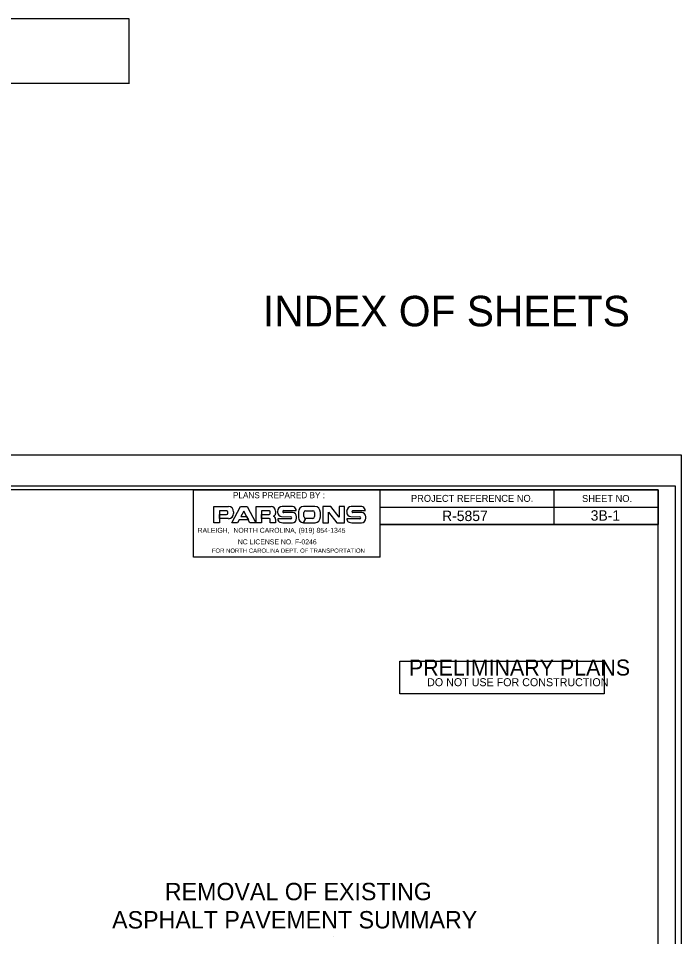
# Model space of a CAD drawing. Extents: x 1729625 to 1732014, y 538843 to 541329.
# Drawn here: x 1731022 to 1731499, y 540668 to 541329 of the extents above; entities that cross this region are included whole.
import ezdxf

# ---------------------------------------------------------------- set-up
doc = ezdxf.new("R2010")
doc.units = 0
for name, color, linetype in [('Old_Level_2', 7, 'Continuous'), ('Prop Horizontal Alignment', 7, 'Continuous'), ('Sheet Cutting Line CELL', 7, 'Continuous'), ('Sheet Data Field CELL', 7, 'Continuous'), ('Sheet Plot Border Inside CELL', 7, 'Continuous'), ('Sheet Plot Border Outside CELL', 7, 'Continuous'), ('Sheet Sticker Exception Certification CELL', 7, 'Continuous'), ('Sheet Sticker Preliminary CELL', 7, 'Continuous'), ('Sheet Summary CELL', 7, 'Continuous')]:
    doc.layers.add(name, color=color, linetype=linetype)

msp = doc.modelspace()

# ---------------------------------------------------------------- linework, layer by layer
at = {"layer": 'Old_Level_2'}
for p, q in [((1731148.02, 540989.91), (1731282.42, 540989.91)), ((1731148.02, 540941.49), (1731148.02, 540989.91)), ((1731282.42, 540941.49), (1731282.42, 540989.91)), ((1731218.6, 540977.9), (1731211.95, 540977.89)), ((1731213.03, 540974.91), (1731222.03, 540974.91)), ((1731235.48, 540977.9), (1731227.35, 540977.89)), ((1731268.36, 540977.9), (1731261.71, 540977.89)), ((1731262.78, 540974.91), (1731271.79, 540974.91)), ((1731172.84, 540973.16), (1731172.84, 540973.85)), ((1731176.92, 540974.07), (1731176.92, 540972.92)), ((1731203.33, 540972.92), (1731203.33, 540974.23)), ((1731207.12, 540974.61), (1731207.12, 540972.85)), ((1731208.6, 540974.31), (1731208.6, 540973.84)), ((1731211.54, 540970.62), (1731218.1, 540970.48)), ((1731219.46, 540973.46), (1731213.03, 540973.46)), ((1731222.31, 540969.48), (1731222.31, 540970.4)), ((1731223.67, 540973.92), (1731223.67, 540970.02)), ((1731227.21, 540966.19), (1731228.76, 540969.33)), ((1731227.63, 540970.56), (1731227.63, 540973.54)), ((1731228.76, 540974.77), (1731234.07, 540974.77)), ((1731235.2, 540973.54), (1731235.2, 540970.56)), ((1731239.45, 540970.32), (1731239.45, 540973.62)), ((1731258.36, 540974.31), (1731258.36, 540973.84)), ((1731261.3, 540970.62), (1731267.86, 540970.48)), ((1731269.21, 540973.46), (1731262.78, 540973.46)), ((1731272.07, 540969.48), (1731272.07, 540970.4)), ((1731212.38, 540966.19), (1731219.25, 540966.19)), ((1731227.2, 540966.19), (1731235.63, 540966.19)), ((1731262.14, 540966.19), (1731269.01, 540966.19)), ((1731282.42, 540941.49), (1731148.02, 540941.49))]:
    msp.add_line(p, q, dxfattribs=at)
for points in [[(1731171.98, 540974.77), (1731166.82, 540974.77), (1731166.82, 540972.09), (1731166.89, 540969.1), (1731166.89, 540966.19), (1731162.73, 540966.19), (1731162.73, 540977.9), (1731173.34, 540977.9)], [(1731202.83, 540974.76), (1731197.04, 540974.76), (1731197.04, 540972.16), (1731197.04, 540969.33), (1731197.04, 540966.2), (1731193.18, 540966.19), (1731193.18, 540977.9), (1731204.04, 540977.9)], [(1731173.34, 540969.1), (1731166.89, 540969.1), (1731166.82, 540972.09), (1731171.84, 540972.09)], [(1731207.12, 540968.72), (1731207.12, 540966.2), (1731203.19, 540966.2), (1731203.19, 540968.87), (1731202.68, 540969.33), (1731197.04, 540969.33), (1731197.04, 540972.16), (1731202.61, 540972.16)], [(1731218.1, 540969.03), (1731208.74, 540969.03), (1731208.74, 540968.79)], [(1731234.07, 540969.33), (1731228.76, 540969.33), (1731227.21, 540966.19), (1731235.63, 540966.19)], [(1731267.86, 540969.03), (1731258.5, 540969.03), (1731258.5, 540968.79)]]:
    msp.add_lwpolyline(points, dxfattribs=at)
for points in [[(1731175.58, 540966.19), (1731182.01, 540977.9), (1731186.69, 540977.9), (1731193.05, 540966.19), (1731188.67, 540966.19), (1731184.21, 540974.38), (1731182.15, 540970.63), (1731186.26, 540970.63), (1731187.6, 540968.18), (1731180.88, 540968.18), (1731179.82, 540966.19)], [(1731241.23, 540977.9), (1731241.23, 540966.19), (1731245.2, 540966.19), (1731245.2, 540973.77), (1731251.28, 540966.19), (1731256.87, 540966.19), (1731256.87, 540977.9), (1731253.05, 540977.9), (1731253.05, 540970.1), (1731246.89, 540977.9)]]:
    msp.add_lwpolyline(points, close=True, dxfattribs=at)
for centre, major_axis, ratio, start_param, end_param in [((1731173.34, 540974.07), (0, 3.83), 0.93676, 4.712389, 6.283185), ((1731204.04, 540974.61), (0, 3.29), 0.934072, 4.712389, 6.283185), ((1731211.96, 540974.3), (0, 3.6), 0.934072, 0, 1.570796), ((1731213.03, 540974.19), (0, 0.727), 0.934072, 0, 3.141593), ((1731218.6, 540972.92), (0, 4.97), 0.934072, 5.902203, 6.283185), ((1731219.32, 540974.84), (0, 2.91), 0.934072, 4.738699, 5.901866), ((1731227.35, 540973.92), (0, 3.98), 0.924824, 0, 1.570796), ((1731235.48, 540973.61), (0, 4.28), 0.924824, 4.712389, 6.283185), ((1731261.71, 540974.3), (0, 3.6), 0.934072, 0, 1.570796), ((1731262.79, 540974.19), (0, 0.727), 0.934072, 0, 3.141593), ((1731268.36, 540972.92), (0, 4.97), 0.934072, 5.902203, 6.283185), ((1731269.07, 540974.84), (0, 2.91), 0.934072, 4.738699, 5.901866), ((1731171.83, 540973.15), (0, 1.07), 0.93676, 3.141593, 4.712389), ((1731171.98, 540973.84), (0, 0.918), 0.93676, 4.712389, 6.283185), ((1731173.34, 540972.92), (0, 3.83), 0.93676, 3.141593, 4.712389), ((1731202.61, 540972.92), (0, 0.765), 0.934072, 3.141593, 4.712389), ((1731202.83, 540974.22), (0, 0.536), 0.934072, 4.712389, 6.283185), ((1731205.26, 540972.85), (0, 1.99), 0.934072, 3.34512, 4.712389), ((1731204.97, 540968.72), (0, 2.3), 0.934072, 4.712389, 5.969561), ((1731211.6, 540973.84), (0, -3.21), 0.934072, 4.712389, 6.260753), ((1731210.95, 540968.79), (0, -2.37), 0.934072, 4.712389, 5.988639), ((1731218.1, 540969.75), (0, 0.727), 0.934072, 3.141593, 6.283185), ((1731219.24, 540969.48), (0, 3.29), 0.934072, 3.141593, 4.712389), ((1731219.46, 540970.4), (0, 3.06), 0.934072, 4.712389, 6.283185), ((1731227.2, 540970.02), (0, -3.83), 0.924824, 4.712389, 6.283185), ((1731228.76, 540973.54), (0, -1.22), 0.924824, 3.141593, 4.712389), ((1731228.76, 540970.55), (0, -1.22), 0.924824, 4.712389, 6.283185), ((1731234.07, 540973.54), (0, 1.22), 0.924824, 4.712389, 6.283185), ((1731234.07, 540970.55), (0, 1.22), 0.924824, 3.141593, 4.712389), ((1731235.62, 540970.32), (0, 4.13), 0.924824, 3.141593, 4.712389), ((1731261.36, 540973.84), (0, -3.21), 0.934072, 4.712389, 6.260753), ((1731260.71, 540968.79), (0, -2.37), 0.934072, 4.712389, 5.988639), ((1731267.86, 540969.75), (0, 0.727), 0.934072, 3.141593, 6.283185), ((1731269, 540969.48), (0, 3.29), 0.934072, 3.141593, 4.712389), ((1731269.22, 540970.4), (0, 3.06), 0.934072, 4.712389, 6.283185), ((1731212.38, 540973.84), (0, 7.65), 0.934072, 2.847261, 3.141593), ((1731262.14, 540973.84), (0, 7.65), 0.934072, 2.847261, 3.141593)]:
    msp.add_ellipse(centre, major_axis=major_axis, ratio=ratio, start_param=start_param, end_param=end_param, dxfattribs=at)
at = {"layer": 'Prop Horizontal Alignment'}
msp.add_line((1731248.61, 540668.22), (1731248.61, 540668.22), dxfattribs=at)
at = {"layer": 'Sheet Cutting Line CELL'}
msp.add_line((1731499.47, 541014.91), (1729815.47, 541014.91), dxfattribs=at)
at = {"layer": 'Sheet Plot Border Inside CELL'}
msp.add_lwpolyline([(1731494.97, 540992.46), (1729828.47, 540992.46), (1729828.47, 539937.36), (1731494.97, 539937.36)], close=True, dxfattribs=at)
at = {"layer": 'Sheet Plot Border Outside CELL'}
msp.add_lwpolyline([(1731499.47, 541014.91), (1729815.47, 541014.91), (1729815.47, 539914.91), (1731499.47, 539914.91)], close=True, dxfattribs=at)
at = {"layer": 'Sheet Sticker Exception Certification CELL'}
for p, q in [((1730701.49, 541329.27), (1731101.56, 541329.27)), ((1731101.56, 541329.24), (1731101.56, 541282.24)), ((1731101.56, 541282.27), (1730701.49, 541282.27))]:
    msp.add_line(p, q, dxfattribs=at)
at = {"layer": 'Sheet Sticker Preliminary CELL'}
msp.add_lwpolyline([(1731296.65, 540843.03), (1731296.65, 540866.53), (1731443.65, 540866.53), (1731443.65, 540843.03)], close=True, dxfattribs=at)
at = {"layer": 'Sheet Summary CELL'}
for p, q in [((1731407.47, 540989.86), (1731407.47, 540964.86)), ((1731282.42, 540977.36), (1731482.47, 540977.36)), ((1731282.42, 540964.86), (1731482.47, 540964.86))]:
    msp.add_line(p, q, dxfattribs=at)
for points in [[(1731482.47, 540989.91), (1729982.47, 540989.91), (1729982.47, 539939.91), (1731482.47, 539939.91)], [(1731282.42, 540989.91), (1731482.47, 540989.91), (1731482.47, 540964.86), (1731282.42, 540964.86)]]:
    msp.add_lwpolyline(points, close=True, dxfattribs=at)

# ---------------------------------------------------------------- texts
at = {"layer": 'Old_Level_2'}
for s, height, rotation, p in [('PLANS PREPARED BY : ', 4.4145, 359.99904, (1731176.49, 540983.81)), ('RALEIGH,  NORTH CAROLINA, (919) 854-1345', 3.5754, 359.99996, (1731151.04, 540958.92)), ('NC LICENSE NO. F-0246', 3.5754, 359.99996, (1731179.98, 540950.6)), ('FOR NORTH CAROLINA DEPT. OF TRANSPORTATION', 3.1013, 359.99995, (1731161.31, 540944.51))]:
    msp.add_text(s, height=height, rotation=rotation, dxfattribs=at).set_placement(p)
at = {"layer": 'Prop Horizontal Alignment'}
for s, p in [('REMOVAL OF EXISTING ', (1731127.44, 540694.39)), ('ASPHALT PAVEMENT SUMMARY', (1731089.52, 540674.07))]:
    msp.add_text(s, height=12.5001, rotation=0.01193, dxfattribs=at).set_placement(p)
at = {"layer": 'Sheet Data Field CELL'}
for s, p in [('R-5857', (1731327.04, 540967.36)), ('3B-1', (1731434, 540967.66))]:
    msp.add_text(s, height=7.5, dxfattribs=at).set_placement(p)
at = {"layer": 'Sheet Sticker Preliminary CELL'}
for s, height, p in [('PRELIMINARY PLANS', 11.52, (1731303.15, 540856.18)), ('DO NOT USE FOR CONSTRUCTION', 5.76, (1731316.25, 540848.48))]:
    msp.add_text(s, height=height, dxfattribs=at).set_placement(p)
at = {"layer": 'Sheet Summary CELL'}
for s, height, p in [('INDEX OF SHEETS', 21.9501, (1731198.02, 541107.58)), ('PROJECT REFERENCE NO.', 5.0001, (1731304.62, 540981.21)), ('SHEET NO.', 5, (1731427.77, 540981.11))]:
    msp.add_text(s, height=height, dxfattribs=at).set_placement(p)

doc.saveas('drawing.dxf')
